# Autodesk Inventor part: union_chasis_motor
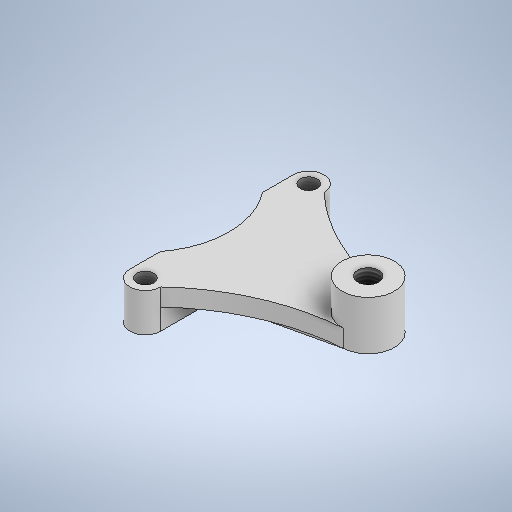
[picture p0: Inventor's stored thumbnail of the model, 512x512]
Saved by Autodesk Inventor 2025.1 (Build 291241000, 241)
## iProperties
Created: 2025-04
Part Number: union_chasis_motor
Material: Genérico
Document SubType Name: Modeling
Designer: Usuario
Density: 1 g/cm^3
Appearance: Valor por defecto
Author: Usuario
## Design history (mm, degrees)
node "Anotaciones"
  node "Cota lineal 1" dims "d124" = 46.87 (derived)
sketch "Boceto1" dims "d64" = 4.85, "d66" = 4.85
  geometry: L1 (4.425, 0)-(4.425, -46.87); L2 (-4.425, 0)-(-4.425, -46.87); L3 (0, 0)-(0, -2.425); L4 (0, -44.445)-(0, -46.87); A1 r 4.425 centre (0, -46.87) between (-4.425, -46.87) and (4.425, -46.87); A2 r 4.425 centre (0, 0) between (4.425, 0) and (-4.425, 0); 2 further points
  constraints: 8 end point, 4 coincident, 4 point on circle, 4 vertical, 2 centre point, 2 vertical alignment, 1 tangent, 4 other
  dimensions: "d65" = 46.87 distance of L3.start L4.end; "d67" = 8.85 diameter of A1; "d68" = 8.85 diameter of A2
extrude "length" new body sketch "Boceto1" distance "d1" = 8 (= EXT_screwDepth); taper "d2" = 0 deg
feature "Rosca4" dims "d69" = 8, "d70" = 0
feature "Rosca5" dims "d71" = 8, "d72" = 0
feature "Engrosado6" dims "d119" = 8, "d120" = 8
node "Plano de trabajo12"
sketch "Boceto10"
  geometry: L1 (0, 0)-(23.435, 0); L2 (23.435, 0)-(23.435, -36.075); L3 (0, 0)-(46.87, 0) reference; L4 (46.87, 0)-(23.435, 0); C1 r 3 at (23.435, -36.075); A1 r 4.425 centre (46.87, 4.425) between (46.87, 0) and (46.87, 8.85) reference; A2 r 7.5 centre (23.435, -36.075) between (15.953, -36.591) and (30.917, -36.591); A3 r 59.473 centre (-43.379, -40.685) between (15.953, -36.591) and (0, 0); A4 r 59.473 centre (90.249, -40.685) between (46.87, 0) and (30.917, -36.591); 1 further point
  constraints: 6 end point, 6 point on circle, 4 centre point, 2 coincident, 2 symmetric about line, 1 tangent, 1 vertical, 1 other
  dimensions: "d125" = 23.435 distance of L1.start L1.end (= 0.5 x dist_tornillos); "d126" = 36.075 distance of L1.end L2.end (= dist_ejes); "d127" = 6 diameter of C1 (= D_screwPulley); "d128" = 15 diameter of A2; "d133" = 4.425 distance of L1.start point (0, 4.425) (derived)
extrude "acopleCarcasaPoleas" join sketch "Boceto10" distance "d129" = 5 (= depthScrewUnion); taper "d130" = 0 deg
feature "Rosca7" dims "d131" = 5, "d132" = 0
feature "Cara para el ángulo de desmoldeo1" dims angle "d134" = 10.5 deg
feature "Engrosado9" dims "d140" = 5, "d141" = 5
fillet "Empalme11" dims "d142" = 0.25
node "Plano de trabajo13"
sketch "Boceto11"
  geometry: C1 r 7.5 at (36.075, -23.435); C2 r 3 at (36.075, -23.435) reference; C3 r 3 at (36.075, -23.435); A1 r 7.5 centre (36.075, -23.435) between (36.591, -30.917) and (36.591, -15.953) reference; 3 further points
  constraints: 2 centre point, 2 coincident
extrude "alargueAcople" join sketch "Boceto11" distance "d143" = 9; taper "d144" = 0 deg
sketch "Boceto12"
  geometry: L1 (36.075, -23.435)-(-27.855, -23.435); C1 r 3 at (36.075, -23.435) reference; C2 r 24 at (-27.855, -23.435); 1 further point
  constraints: 2 end point, 1 centre point, 1 coincident, 1 horizontal
  dimensions: "d146" = 63.93 distance of L1.start L1.end (= dist_shaft); "d147" = 48 diameter of C2 (= D_pulleyShaft)
extrude "poleaShaft" cut sketch "Boceto12" extent not by distance; stored distance "d148" = 9; taper "d149" = 0 deg
node "Sólido2"
other parameters: "EXT_screwDepth" = 8 [user parameter; used in 1 equation term], "D_screwHead" = 9.9 [user parameter], "D_cableIn" = 4 [user parameter], "D_screw" = 4.85 [user parameter], "D_amongCables" = 7 [user parameter], "D_screwPulley" = 6 [user parameter; used in 1 equation term], "depthScrewUnion" = 5 [user parameter; used in 1 equation term], "dist_tornillos" = 46.87 [user parameter; used in 1 equation term], "dist_ejes" = 36.075 [user parameter; used in 1 equation term], "dist_shaft" = 63.93 [user parameter; used in 1 equation term], "D_pulleyShaft" = 48 [user parameter; used in 1 equation term], "d122" = 0 (derived)
